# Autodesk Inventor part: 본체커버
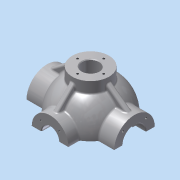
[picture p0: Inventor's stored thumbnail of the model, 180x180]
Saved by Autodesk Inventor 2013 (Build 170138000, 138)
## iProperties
Created: 2015-12
Part Number: 본체커버
Material: 알루미늄 6061
Document SubType Name: Modeling
Designer: mduedu
Density: 1 g/cm^3
Mass: 217.614 g
Surface Area: 460.056 cm^2
Volume: 217.614 cm^3
Author: mduedu
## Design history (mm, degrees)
sketch "스케치1"
  geometry: L1 (-53, 0)-(53, 0); A1 r 53 centre (0, 0) between (53, 0) and (-53, 0); 2 further points
  constraints: 2 coincident, 2 end point, 2 point on circle, 1 centre point, 1 horizontal, 1 midpoint
  dimensions: "d0" = 53 radius of A1
revolve "회전1" sketch "스케치1" stored, may be unused: angle "d2" = 90 deg
feature "쉘1" dims "d11" = 10
node "작업 평면1"
sketch "스케치2"
  geometry: C1 r 31 at (0, 0); 1 further point
  constraints: 1 centre point, 1 coincident
  dimensions: "d4" = 62 diameter of C1
extrude "돌출1" join sketch "스케치2" stored distance "d5" = 10; taper "d6" = 0 deg
node "작업 평면2"
sketch "스케치3"
  geometry: C1 r 28 at (0, 0); 1 further point
  constraints: 1 centre point, 1 coincident
  dimensions: "d8" = 56 diameter of C1
extrude "돌출2" join sketch "스케치3" stored distance "d9" = 10; taper "d10" = 0 deg
hole "구멍1" diameter "d14" = 35; stored, may be unused: countersink angle "d18" = 90 deg, drill point angle "d20" = 0 deg; dims "d12" = 10, "d13" = 10, "d15" = 6, "d16" = 4, "d17" = 2, "d19" = 16
hole "구멍2" diameter "d23" = 27; stored, may be unused: countersink angle "d27" = 90 deg, drill point angle "d29" = 0 deg; dims "d21" = 10, "d22" = 10, "d24" = 6, "d25" = 4, "d26" = 2, "d28" = 16
fillet "모깎기1" dims "d30" = 0.3
hole "구멍3" diameter "d33" = 26; stored, may be unused: countersink angle "d37" = 90 deg, drill point angle "d39" = 0 deg; dims "d31" = 10, "d32" = 10, "d34" = 6, "d35" = 4, "d36" = 2, "d38" = 16
chamfer "모따기1" distance "d40" = 1; stored, may be unused: second distance "d41" = 2, angle "d42" = 45 deg
sketch "스케치4"
  geometry: L1 (0, 0)-(0, -25); L2 (0, 0)-(-17.678, -17.678); A1 r 25 centre (0, 0) between (-17.678, -17.678) and (0, -25); 1 further point
  constraints: 4 end point, 2 point on circle, 1 centre point, 1 coincident, 1 vertical
  dimensions: "d43" = 50 diameter of A1; "d47" = 45 deg angle of L1 L2
hole "구멍4" sketch "스케치4" at (-17.678, -17.678) diameter "d49" = 3.242; stored, may be unused: countersink angle "d53" = 90 deg, drill point angle "d55" = 118 deg; dims "d50" = 11, "d51" = 4, "d52" = 2, "d54" = 13
sketch "스케치5"
  geometry: L1 (0, 0)-(0, -20); L2 (0, 0)-(-14.142, -14.142); A1 r 20 centre (0, 0) between (0, -20) and (-14.142, -14.142); 2 further points
  constraints: 4 end point, 2 coincident, 2 point on circle, 1 centre point, 1 vertical
  dimensions: "d59" = 40 diameter of A1; "d65" = 45 deg angle of L1 L2
hole "구멍5" sketch "스케치5" at (-14.142, -14.142) diameter "d67" = 3.242; stored, may be unused: countersink angle "d71" = 90 deg, drill point angle "d73" = 118 deg; dims "d68" = 8, "d69" = 4, "d70" = 2, "d72" = 10
node "작업 평면3"
sketch "스케치6"
  geometry: C1 r 65 at (0, 0); 1 further point
  constraints: 1 centre point, 1 coincident
  dimensions: "d78" = 130 diameter of C1
extrude "돌출3" join sketch "스케치6" distance "d80" = 10; taper "d81" = 0 deg
sketch "스케치7"
  geometry: C1 r 20 at (0, 0); 1 further point
  constraints: 1 centre point, 1 coincident
  dimensions: "d82" = 40 diameter of C1
extrude "돌출4" join sketch "스케치7" stored distance "d84" = 10; taper "d85" = 0 deg
sketch "스케치8"
  geometry: 2 further points
  constraints: 1 coincident
hole "구멍6" sketch "스케치8" at (0, 0) diameter "d86" = 20; stored, may be unused: countersink angle "d90" = 90 deg, drill point angle "d92" = 118 deg; dims "d87" = 7, "d88" = 40, "d89" = 5, "d91" = 10
fillet "모깎기2" dims "d93" = 0.3
sketch "스케치9"
  geometry: L1 (65, -75)-(-65, -75) reference; L2 (-45, -75)-(-38.245, -36.692); A1 r 53 centre (0, 0) between (42.988, 31) and (42.988, -31) reference; 1 further point
  constraints: 2 end point, 1 point on circle, 1 point on line
  dimensions: "d94" = 45 horizontal distance of L2.start point (0, 0); "d95" = 80 deg angle of L2 L1
feature "리브1" sketch "스케치9" dims "d96" = 1, "d97" = 8, "d98" = 0, "d99" = 0, "d100" = 1, "d101" = 1
sketch "스케치10"
  geometry: L1 (0, 0)-(0, -55); L2 (0, 0)-(-38.891, -38.891); A1 r 55 centre (0, 0) between (0, -55) and (-38.891, -38.891); 2 further points
  constraints: 4 end point, 2 coincident, 2 point on circle, 1 centre point, 1 vertical
  dimensions: "d105" = 110 diameter of A1; "d107" = 45 deg angle of L1 L2
hole "구멍7" sketch "스케치10" at (-38.891, -38.891) diameter "d109" = 10; stored, may be unused: countersink angle "d113" = 90 deg, drill point angle "d115" = 118 deg; dims "d110" = 7, "d111" = 40, "d112" = 5, "d114" = 10
fillet "모깎기3" dims "d120" = 3
fillet "모깎기4" dims "d121" = 3, "d122" = 3
fillet "모깎기5" dims "d123" = 3
fillet "모깎기6" dims "d124" = 3
sketch "스케치11"
  geometry: C1 r 5 at (-38.891, 38.891) reference; C2 r 5 at (38.891, 38.891) reference; C3 r 5 at (38.891, -38.891) reference; C4 r 5 at (-38.891, -38.891) reference; C5 r 20 at (0, 0) reference; C6 r 65 at (0, 0) reference; 1 further point
  constraints: 3 other
feature "엠보싱1" sketch "스케치11" dims "d125" = 0.5, "d126" = 0
sketch "스케치12"
  geometry: L1 (0, 100)-(0, -100); L2 (0, 100)-(-150, 100); L3 (-150, 100)-(-150, -100); L4 (-150, -100)-(0, -100); 2 further points
  constraints: 8 end point, 3 perpendicular, 1 coincident, 1 midpoint, 1 vertical
  dimensions: "d127" = 200 distance of L2.end L3.end; "d129" = 150 distance of L3.end L1.end
extrude "돌출5" cut sketch "스케치12" stored distance "d130" = 10; taper "d131" = 0 deg
sketch "스케치13"
  geometry: C1 r 7 at (0, -53); A1 r 53 centre (0, 0) between (-42.113, -32.179) and (42.113, -32.179) reference; 1 further point
  constraints: 1 centre point, 1 point on circle
  dimensions: "d132" = 14 diameter of C1
extrude "돌출6" join sketch "스케치13" distance "d133" = 5; taper "d134" = 0 deg
sketch "스케치14"
  geometry: C1 r 7 at (0, 0) reference; 1 further point
extrude "돌출7" cut sketch "스케치14" stored distance "d135" = 5; taper "d136" = 0 deg
sketch "스케치15"
  geometry: C1 r 2.25 at (0, 53); A1 r 7 centre (0, 53) between (6.965, 52.302) and (-6.965, 52.302) reference; 1 further point
  constraints: 1 centre point, 1 coincident
  dimensions: "d139" = 4.5 diameter of C1
extrude "돌출8" cut sketch "스케치15" stored distance "d141" = 5; taper "d142" = 0 deg
fillet "모깎기7" dims "d143" = 3
fillet "모깎기8" dims "d144" = 1
fillet "모깎기9" dims "d145" = 1
fillet "모깎기10" dims "d146" = 1
node "작업 평면4"
sketch "스케치16"
  geometry: C1 r 28 at (0, 0); 1 further point
  constraints: 1 centre point, 1 coincident
  dimensions: "d148" = 56 diameter of C1
extrude "돌출9" join sketch "스케치16" stored distance "d150" = 5; taper "d151" = 0 deg
hole "구멍8" diameter "d154" = 26; stored, may be unused: countersink angle "d158" = 90 deg, drill point angle "d160" = 118 deg; dims "d152" = 10, "d153" = 10, "d155" = 6, "d156" = 4, "d157" = 2, "d159" = 8
sketch "스케치17" dims "d161" = 40
  geometry: 3 further points
  constraints: 2 vertical alignment, 1 coincident, 2 other
hole "구멍9" sketch "스케치17" at (0, 20) diameter "d163" = 3.242; stored, may be unused: countersink angle "d167" = 90 deg, drill point angle "d169" = 118 deg; dims "d164" = 8, "d165" = 4, "d166" = 2, "d168" = 10
fillet "모깎기11" dims "d173" = 3
chamfer "모따기2" distance "d174" = 1; stored, may be unused: second distance "d175" = 2, angle "d176" = 45 deg
sketch "스케치18"
  geometry: L1 (28, 62)-(28, 46.637) reference; L2 (67, 31)-(44.497, 31) reference; L3 (28, 55)-(60, 31); L4 (-28, 62)-(28, 62) reference; L5 (67, 31)-(67, 0) reference; 1 further point
  constraints: 2 end point, 2 point on line
  dimensions: "d177" = 7 distance from line of L3.start L4; "d178" = 7 distance from line of L3.end L5
feature "리브2" sketch "스케치18" dims "d179" = 1, "d180" = 8, "d181" = 0, "d182" = 0, "d183" = 1, "d184" = 1
fillet "모깎기12" dims "d185" = 3
fillet "모깎기13" dims "d186" = 3
sketch "스케치19"
  geometry: L1 (62, 28)-(46.637, 28) reference; L2 (28, 62)-(28, 46.637) reference; L3 (55, 28)-(28, 55); L4 (0, 62)-(28, 62) reference; L5 (62, 28)-(62, -28) reference; 1 further point
  constraints: 2 end point, 2 point on line
  dimensions: "d187" = 7 distance from line of L3.end L4; "d188" = 7 distance from line of L3.start L5
feature "리브3" sketch "스케치19" dims "d189" = 1, "d190" = 8, "d191" = 0, "d192" = 0, "d193" = 1, "d194" = 1
fillet "모깎기14" dims "d195" = 3
fillet "모깎기15" dims "d196" = 3
node "솔리드1"
mirror "대칭1"
mirror "대칭2"
pattern_circular "원형 패턴1" dims angle "d57" = 360 deg
mirror "대칭3"
pattern_circular "원형 패턴2" dims angle "d75" = 360 deg
pattern_circular "원형 패턴3" dims angle "d103" = 360 deg
pattern_circular "원형 패턴4" dims angle "d118" = 360 deg
pattern_circular "원형 패턴5" dims angle "d171" = 360 deg
mirror "대칭4"
node "투영된 루프1"
other parameters: "d3" = 67, "d7" = 62, "d77" = -85, "d147" = 62
